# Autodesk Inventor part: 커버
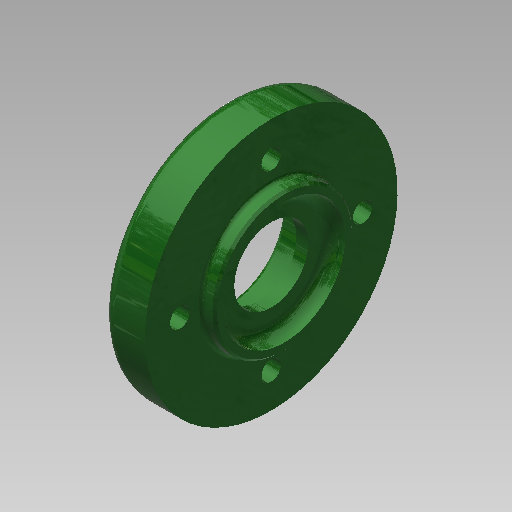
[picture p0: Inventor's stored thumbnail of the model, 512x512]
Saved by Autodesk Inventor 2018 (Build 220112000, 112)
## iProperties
Created: 2015-11
Part Number: 커버
Material: 알루미늄 6061
Document SubType Name: Modeling
Designer: mduedu
Density: 2.71 g/cm^3
Mass: 57.8273 g
Surface Area: 81.1807 cm^2
Volume: 21.3385 cm^3
Appearance: 매끄러움 - 짙은 산림 녹색
Author: mduedu
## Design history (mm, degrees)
sketch "스케치1"
  geometry: L1 (-6.5, 0)-(6.5, 0); L2 (-6.5, 0)-(-6.5, 29); L3 (-6.5, 29)-(3.5, 29); L4 (3.5, 29)-(3.5, 16); L5 (3.5, 16)-(6.5, 16); L6 (6.5, 16)-(6.5, 0); 2 further points
  constraints: 12 end point, 3 perpendicular, 2 parallel, 1 coincident, 1 horizontal, 1 midpoint
  dimensions: "d0" = 13 distance of L1.start L1.end; "d1" = 58 diameter of L3 L1; "d2" = 3 distance of L4.end L5.end; "d3" = 32 diameter of L5 L1
revolve "회전1" sketch "스케치1" stored, may be unused: angle "d4" = 90 deg
hole "구멍1" diameter "d7" = 28; stored, may be unused: countersink angle "d11" = 90 deg, drill point angle "d13" = 0 deg; dims "d8" = 6, "d9" = 4, "d10" = 2, "d12" = 3, "d65" = 10, "d66" = 10
hole "구멍2" diameter "d16" = 25; stored, may be unused: countersink angle "d20" = 90 deg, drill point angle "d22" = 0 deg; dims "d17" = 6, "d18" = 4, "d19" = 2, "d21" = 7.3, "d67" = 10, "d68" = 10
hole "구멍3" diameter "d25" = 17; stored, may be unused: countersink angle "d29" = 90 deg, drill point angle "d31" = 0 deg; dims "d23" = 10, "d24" = 10, "d26" = 6, "d27" = 4, "d28" = 2, "d30" = 4.2
chamfer "모따기1" distance "d32" = 0.7; stored, may be unused: second distance "d33" = 2, angle "d34" = 30 deg
fillet "모깎기1" dims "d35" = 0.2
fillet "모깎기2" dims "d36" = 3
fillet "모깎기3" dims "d37" = 3
fillet "모깎기4" dims "d38" = 1
sketch "스케치3" dims "d61" = 42
  geometry: C1 r 29 at (0, 0) reference; 2 further points
  constraints: 2 vertical alignment, 1 coincident, 2 other
hole "구멍4" sketch "스케치3" at (0, -21) diameter "d44" = 4.5; stored, may be unused: countersink angle "d48" = 90 deg, drill point angle "d50" = 0 deg; dims "d45" = 6, "d46" = 8, "d47" = 4.6, "d49" = 8
chamfer "모따기2" distance "d62" = 0.5; stored, may be unused: second distance "d63" = 2, angle "d64" = 45 deg
node "솔리드1"
pattern_circular "원형 패턴1" dims angle "d54" = 360 deg
